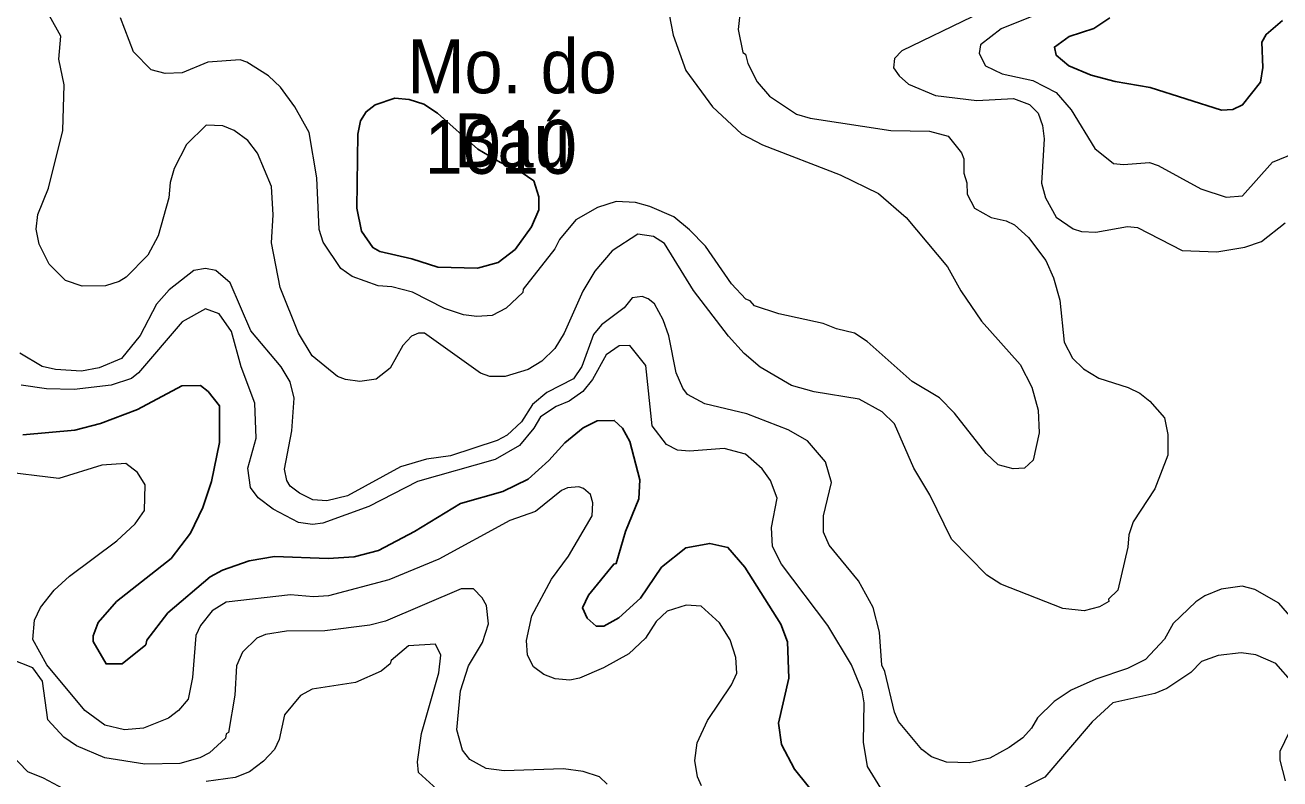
# Model space of a CAD drawing. Extents: x 447.8 to 473.9, y 7733.1 to 7760.8.
# Drawn here: x 457.538 to 459.4, y 7756.505 to 7757.624 of the extents above; entities that cross this region are included whole.
import ezdxf
from ezdxf.enums import TextEntityAlignment as Align

# ---------------------------------------------------------------- set-up
doc = ezdxf.new("R2010")
doc.units = 0
doc.header["$LTSCALE"] = 0.032
doc.layers.add('1', color=7, linetype='Continuous', lineweight=25)
doc.layers.add('2', color=7, linetype='Continuous', lineweight=13)
doc.layers.add('21', color=7, linetype='Continuous')
doc.layers.add('27', color=7, linetype='Continuous')

msp = doc.modelspace()

# ---------------------------------------------------------------- linework, layer by layer
at = {"layer": '1'}
for points in [[(459.4043, 7757.6305), (459.38, 7757.6098), (459.3736, 7757.5982), (459.375, 7757.5608), (459.3716, 7757.5389), (459.3451, 7757.5054), (459.3305, 7757.4984), (459.3139, 7757.4976), (459.208, 7757.5312), (459.1558, 7757.5399), (459.1201, 7757.5495), (459.087, 7757.5633), (459.0683, 7757.5789), (459.0657, 7757.5909), (459.0874, 7757.6065), (459.1242, 7757.6186), (459.148, 7757.6342)], [(457.5343, 7757.0158), (457.6113, 7757.0229), (457.6497, 7757.0324), (457.7043, 7757.0533), (457.7704, 7757.0886), (457.7978, 7757.0892), (457.8094, 7757.08), (457.8264, 7757.059), (457.8264, 7757.0045), (457.8144, 7756.9468), (457.8014, 7756.908), (457.7831, 7756.8699), (457.7544, 7756.8324), (457.6731, 7756.7685), (457.6461, 7756.7375), (457.6389, 7756.7176), (457.6389, 7756.7091), (457.6579, 7756.6759), (457.6818, 7756.6759), (457.7169, 7756.7043), (457.7183, 7756.7111), (457.7497, 7756.7515), (457.8122, 7756.8052), (457.8309, 7756.8152), (457.8701, 7756.829), (457.9079, 7756.8353), (457.9877, 7756.8323), (458.0262, 7756.8349), (458.0621, 7756.8442), (458.1157, 7756.8726), (458.184, 7756.9139), (458.2468, 7756.9317), (458.2846, 7756.9499), (458.315, 7756.9776), (458.3389, 7757.004), (458.3659, 7757.0261), (458.3871, 7757.0365), (458.4123, 7757.0372), (458.4246, 7757.0258), (458.4356, 7757.0061), (458.45, 7756.9488), (458.4485, 7756.921), (458.4287, 7756.8722), (458.4152, 7756.8251), (458.4114, 7756.8238), (458.3738, 7756.7781), (458.3653, 7756.7591), (458.372, 7756.7439), (458.3852, 7756.7321), (458.3968, 7756.732), (458.4191, 7756.7442), (458.4514, 7756.7733), (458.4824, 7756.8196), (458.5183, 7756.8482), (458.5539, 7756.8546), (458.581, 7756.8487), (458.6061, 7756.8196), (458.6597, 7756.735), (458.6695, 7756.7087), (458.6712, 7756.6547), (458.6561, 7756.588), (458.6603, 7756.5563), (458.6799, 7756.5197), (458.7448, 7756.439)]]:
    msp.add_lwpolyline(points, dxfattribs=at)
msp.add_lwpolyline([(458.1497, 7757.4932), (458.1293, 7757.5062), (458.1078, 7757.5131), (458.0866, 7757.5152), (458.0573, 7757.5055), (458.044, 7757.4952), (458.0357, 7757.4814), (458.0317, 7757.4618), (458.0301, 7757.3521), (458.037, 7757.3179), (458.0536, 7757.2935), (458.0643, 7757.2876), (458.1116, 7757.2771), (458.1505, 7757.2647), (458.2092, 7757.2631), (458.24, 7757.2716), (458.265, 7757.2909), (458.2896, 7757.3242), (458.3004, 7757.3496), (458.3004, 7757.3689), (458.2928, 7757.3924), (458.266, 7757.4107), (458.2435, 7757.4196), (458.2098, 7757.4395)], close=True, dxfattribs=at)
at = {"layer": '2'}
for points in [[(459.0644, 7757.2487), (459.0736, 7757.2158), (459.0803, 7757.1531), (459.0924, 7757.1294), (459.1087, 7757.1139), (459.1316, 7757.0998), (459.175, 7757.0861), (459.1923, 7757.0775), (459.2073, 7757.0656), (459.229, 7757.0408), (459.2341, 7757.0163), (459.234, 7756.9856), (459.2147, 7756.9356), (459.1825, 7756.8869), (459.176, 7756.8672), (459.1746, 7756.849), (459.1596, 7756.7856), (459.1461, 7756.772), (459.1463, 7756.7687), (459.1325, 7756.7606), (459.1096, 7756.7545), (459.0779, 7756.7584), (458.9859, 7756.7944), (458.9652, 7756.8077), (458.913, 7756.8608), (458.8809, 7756.9269), (458.8571, 7756.9661), (458.8285, 7757.0323), (458.8101, 7757.0501), (458.7758, 7757.0685), (458.7092, 7757.0796), (458.6752, 7757.0892), (458.6289, 7757.1162), (458.6049, 7757.1366), (458.5819, 7757.1622), (458.5298, 7757.2297), (458.487, 7757.2995), (458.4706, 7757.31), (458.4473, 7757.3134), (458.4089, 7757.2887), (458.3832, 7757.2584), (458.3654, 7757.2288), (458.338, 7757.1667), (458.324, 7757.1438), (458.3047, 7757.1252), (458.2844, 7757.1125), (458.2503, 7757.1024), (458.2276, 7757.1024), (458.2139, 7757.1071), (458.1306, 7757.1664), (458.1214, 7757.1664), (458.111, 7757.1624), (458.0983, 7757.1483), (458.0795, 7757.1149), (458.0589, 7757.0984), (458.0343, 7757.0951), (458.0131, 7757.0977), (458.0012, 7757.1024), (457.9636, 7757.133), (457.9433, 7757.1667), (457.9161, 7757.2344), (457.9034, 7757.3004), (457.9058, 7757.3423), (457.9033, 7757.3841), (457.8827, 7757.4335), (457.8684, 7757.4523), (457.8479, 7757.4674), (457.8314, 7757.4742), (457.8066, 7757.4754), (457.7771, 7757.4464), (457.7589, 7757.4111), (457.7528, 7757.3899), (457.7511, 7757.3672), (457.7351, 7757.311), (457.72, 7757.2821), (457.6875, 7757.2497), (457.6775, 7757.2431), (457.6568, 7757.237), (457.6221, 7757.2363), (457.5976, 7757.2448), (457.5732, 7757.2688), (457.5585, 7757.2986), (457.5539, 7757.3207), (457.5563, 7757.3425), (457.5724, 7757.3815), (457.5938, 7757.4675), (457.5955, 7757.5348), (457.5876, 7757.5733), (457.5907, 7757.607), (457.5572, 7757.6678)], [(458.4878, 7757.6705), (458.4998, 7757.6086), (458.5183, 7757.5565), (458.5579, 7757.5026), (458.601, 7757.4623), (458.6324, 7757.446), (458.7476, 7757.4016), (458.8043, 7757.374), (458.8455, 7757.3384), (458.9069, 7757.2651), (458.9267, 7757.2295), (458.9572, 7757.1843), (459.0149, 7757.1202), (459.0319, 7757.0865), (459.0416, 7757.0526), (459.0432, 7757.0189), (459.0342, 7756.9783), (459.0214, 7756.9662), (459.0044, 7756.9653), (458.9822, 7756.9711), (458.9641, 7756.9883), (458.9171, 7757.0481), (458.8952, 7757.0708), (458.8546, 7757.0948), (458.7878, 7757.1542), (458.7691, 7757.1667), (458.7421, 7757.1728), (458.7223, 7757.1809), (458.6565, 7757.1954), (458.6203, 7757.2073), (458.6142, 7757.2145), (458.6075, 7757.2169), (458.5864, 7757.2397), (458.5475, 7757.2957), (458.5241, 7757.3201), (458.5007, 7757.3391), (458.465, 7757.3544), (458.4436, 7757.3604), (458.4149, 7757.362), (458.3872, 7757.3531), (458.3552, 7757.3345), (458.3311, 7757.3057), (458.3242, 7757.2916), (458.2768, 7757.232), (458.2765, 7757.2269), (458.2518, 7757.2038), (458.2309, 7757.1926), (458.2084, 7757.1913), (458.1884, 7757.1938), (458.1601, 7757.2032), (458.1129, 7757.2272), (458.082, 7757.2352), (458.0618, 7757.237), (458.023, 7757.2509), (458.0063, 7757.2624), (457.9801, 7757.3018), (457.974, 7757.3203), (457.9708, 7757.397), (457.9595, 7757.4643), (457.9382, 7757.5025), (457.9167, 7757.5314), (457.8988, 7757.5486), (457.8668, 7757.5687), (457.8569, 7757.572), (457.8088, 7757.5688), (457.771, 7757.553), (457.7457, 7757.5516), (457.7246, 7757.5574), (457.6983, 7757.5838), (457.679, 7757.6342)], [(458.5998, 7757.6485), (458.596, 7757.617), (458.6031, 7757.583), (458.6071, 7757.5804), (458.6104, 7757.5666), (458.6242, 7757.5397), (458.6427, 7757.5181), (458.6828, 7757.4917), (458.703, 7757.4855), (458.8229, 7757.4671), (458.8801, 7757.4662), (458.9077, 7757.4589), (458.9278, 7757.4339), (458.931, 7757.425), (458.9311, 7757.4041), (458.9358, 7757.3895), (458.9359, 7757.3728), (458.9471, 7757.3518), (458.9716, 7757.3384)], [(458.9436, 7757.636), (458.839, 7757.5854), (458.8284, 7757.5741), (458.827, 7757.5602), (458.8351, 7757.5485), (458.8492, 7757.536), (458.889, 7757.5193), (458.9507, 7757.512), (459.0047, 7757.5145), (459.0285, 7757.5056), (459.0414, 7757.4928), (459.048, 7757.4745), (459.0503, 7757.4549), (459.0465, 7757.3893), (459.0526, 7757.3675), (459.0682, 7757.3386), (459.0933, 7757.3213), (459.1059, 7757.3176), (459.1273, 7757.3164), (459.174, 7757.325), (459.1888, 7757.3235), (459.2554, 7757.2894), (459.3068, 7757.2875), (459.3484, 7757.2941), (459.3731, 7757.3026), (459.4083, 7757.3301)], [(459.0347, 7757.6375), (458.9868, 7757.6182)], [(458.9868, 7757.6182), (458.9561, 7757.5943), (458.954, 7757.5813), (458.9632, 7757.5634), (458.988, 7757.5515), (459.0338, 7757.5413)], [(459.0338, 7757.5413), (459.0684, 7757.5236), (459.0903, 7757.4979), (459.1257, 7757.4406), (459.1536, 7757.4182), (459.1683, 7757.4166), (459.2069, 7757.4199), (459.2198, 7757.4155), (459.2831, 7757.3807), (459.3205, 7757.3685), (459.3447, 7757.3704), (459.3896, 7757.4203), (459.4416, 7757.4416)], [(458.9716, 7757.3384), (458.994, 7757.3335), (459.0066, 7757.3273), (459.027, 7757.3086), (459.053, 7757.2743), (459.0644, 7757.2487)], [(458.3121, 7757.0787), (458.291, 7757.061), (458.2747, 7757.0349), (458.2534, 7757.0152), (458.2386, 7757.0075), (458.1691, 7756.9844), (458.1336, 7756.9795), (458.0951, 7756.9682), (458.0162, 7756.9254), (457.9854, 7756.918), (457.9648, 7756.9194), (457.9448, 7756.9293), (457.9313, 7756.9398), (457.926, 7756.9481), (457.9227, 7756.965), (457.9338, 7757.0218), (457.937, 7757.0702), (457.9313, 7757.0946), (457.9177, 7757.1167), (457.8728, 7757.1699), (457.842, 7757.2413), (457.8206, 7757.2598), (457.8054, 7757.2625), (457.7883, 7757.2594), (457.7516, 7757.2311), (457.7327, 7757.2097), (457.7086, 7757.1633), (457.6807, 7757.1289), (457.6476, 7757.1151), (457.6215, 7757.1104), (457.5828, 7757.1127), (457.5629, 7757.117), (457.53, 7757.1369)], [(459.4215, 7756.74), (459.3988, 7756.766), (459.363, 7756.7864), (459.3442, 7756.7913), (459.3131, 7756.7866), (459.2891, 7756.7771), (459.2756, 7756.7679), (459.2419, 7756.7359), (459.229, 7756.7125), (459.2008, 7756.6825), (459.1741, 7756.6692), (459.1269, 7756.6535), (459.0906, 7756.6372), (459.0654, 7756.6203), (459.0405, 7756.5962), (459.0316, 7756.5808), (459.0188, 7756.5665), (458.9986, 7756.5518), (458.97, 7756.5362), (458.939, 7756.5292), (458.9054, 7756.53), (458.8832, 7756.5379), (458.8689, 7756.5488), (458.8344, 7756.5907), (458.8282, 7756.6043), (458.8139, 7756.6646), (458.8093, 7756.674), (458.8058, 7756.723), (458.7967, 7756.7598), (458.7746, 7756.7991), (458.7312, 7756.8521), (458.7227, 7756.8715), (458.7227, 7756.8955), (458.7347, 7756.9452), (458.7258, 7756.9756), (458.6993, 7757.0069), (458.6705, 7757.023), (458.6088, 7757.0467), (458.5468, 7757.062), (458.5209, 7757.0755), (458.514, 7757.0849), (458.5043, 7757.1077), (458.4934, 7757.1629), (458.4848, 7757.1866), (458.4719, 7757.21), (458.4628, 7757.2177), (458.4535, 7757.2208), (458.4389, 7757.2192), (458.4267, 7757.204)], [(457.8054, 7757.2029), (457.771, 7757.1836), (457.7061, 7757.1079), (457.6955, 7757.0996), (457.6653, 7757.0893), (457.6107, 7757.0831), (457.5693, 7757.0839), (457.5316, 7757.0897)], [(457.8808, 7757.011), (457.8785, 7757.063), (457.8584, 7757.1167), (457.844, 7757.1691), (457.8258, 7757.1954), (457.8054, 7757.2029)], [(458.4267, 7757.204), (458.3931, 7757.1791), (458.3812, 7757.1648), (458.3643, 7757.117), (458.3519, 7757.0991), (458.3121, 7757.0787)], [(458.8081, 7756.4918), (458.7884, 7756.5236), (458.782, 7756.5597), (458.7832, 7756.6183), (458.7802, 7756.6358), (458.7646, 7756.6748), (458.7291, 7756.7329), (458.6605, 7756.8241), (458.647, 7756.8499), (458.6457, 7756.8781), (458.6542, 7756.9218), (458.6441, 7756.948), (458.6318, 7756.9652), (458.6069, 7756.987), (458.5754, 7756.9955), (458.5237, 7756.9918), (458.5063, 7756.9931), (458.49, 7757.0015), (458.4684, 7757.0293), (458.4592, 7757.1185), (458.4353, 7757.1484), (458.4197, 7757.1477), (458.4002, 7757.1345), (458.3798, 7757.0981), (458.3658, 7757.0799), (458.3453, 7757.0656), (458.3262, 7757.0579), (458.3026, 7757.0427), (458.2929, 7757.0258), (458.2718, 7756.9998), (458.2356, 7756.9793), (458.1199, 7756.9467), (458.0478, 7756.9093), (457.9798, 7756.8846), (457.9642, 7756.8828), (457.9433, 7756.8858), (457.906, 7756.9053), (457.8835, 7756.9225), (457.8721, 7756.9375), (457.8682, 7756.9664), (457.8808, 7757.011)], [(457.7043, 7756.9599), (457.687, 7756.9733), (457.6516, 7756.9708), (457.5875, 7756.9509), (457.4974, 7756.9621)], [(457.6033, 7756.8062), (457.6739, 7756.8584), (457.7009, 7756.8837), (457.715, 7756.9035), (457.7157, 7756.9417), (457.7043, 7756.9599)], [(458.5418, 7756.4953), (458.5357, 7756.5083), (458.5319, 7756.5325), (458.5351, 7756.559), (458.5505, 7756.5921), (458.5865, 7756.6449), (458.5942, 7756.6621), (458.5927, 7756.6855), (458.5844, 7756.7118), (458.5684, 7756.7371), (458.5412, 7756.7615), (458.5189, 7756.7631), (458.4909, 7756.7544), (458.4745, 7756.7389), (458.4588, 7756.7143), (458.4338, 7756.6908), (458.3965, 7756.6699), (458.3605, 7756.6549), (458.3462, 7756.6519), (458.3245, 7756.654), (458.3077, 7756.6604), (458.2924, 7756.6718), (458.2834, 7756.6887), (458.2818, 7756.7108), (458.29, 7756.7471), (458.3191, 7756.8019), (458.3442, 7756.8357), (458.3795, 7756.8956), (458.3803, 7756.9147), (458.3771, 7756.9272), (458.3666, 7756.9363), (458.3597, 7756.9386), (458.343, 7756.9371), (458.3341, 7756.9333), (458.2953, 7756.902), (458.2573, 7756.8889), (458.1517, 7756.8312), (458.0775, 7756.8007), (457.988, 7756.7768), (457.9656, 7756.7753), (457.9315, 7756.7784), (457.836, 7756.7678), (457.8154, 7756.7546), (457.798, 7756.7329), (457.7912, 7756.7182), (457.7863, 7756.6559), (457.7799, 7756.6238), (457.7653, 7756.6067), (457.7503, 7756.5954), (457.7133, 7756.5806), (457.685, 7756.5782), (457.6562, 7756.5852), (457.6261, 7756.6069), (457.5697, 7756.6745), (457.5491, 7756.7122), (457.5516, 7756.7407), (457.5607, 7756.7595), (457.581, 7756.7854), (457.6033, 7756.8062)], [(458.4018, 7756.4978), (458.3901, 7756.5086), (458.3659, 7756.5162), (458.337, 7756.5203), (458.2489, 7756.5172), (458.2221, 7756.5209), (458.1976, 7756.5341), (458.1869, 7756.5482), (458.1784, 7756.578), (458.184, 7756.6359), (458.1958, 7756.6731), (458.2167, 7756.7077), (458.2256, 7756.7354), (458.2226, 7756.7625), (458.2161, 7756.7738), (458.2031, 7756.7871), (458.1852, 7756.7871), (458.0724, 7756.7395), (458.0492, 7756.7335), (457.9826, 7756.7248), (457.9255, 7756.7247), (457.8946, 7756.7198), (457.8818, 7756.7143), (457.8605, 7756.6932), (457.8513, 7756.6733), (457.8489, 7756.6297)], [(458.1597, 7756.4802), (458.1216, 7756.515), (458.12, 7756.5306), (458.1261, 7756.5725), (458.1518, 7756.6627), (458.1549, 7756.6888), (458.1471, 7756.7051), (458.107, 7756.703), (458.0809, 7756.681), (458.0797, 7756.6762), (458.0663, 7756.6654), (458.0281, 7756.6486), (457.9637, 7756.6387), (457.9465, 7756.629), (457.9225, 7756.6002), (457.9146, 7756.5637), (457.9079, 7756.549), (457.8916, 7756.5317), (457.8707, 7756.516), (457.8493, 7756.5073), (457.8063, 7756.5013)], [(457.797, 7756.5366), (457.7675, 7756.5284), (457.7153, 7756.5274), (457.6562, 7756.5365), (457.6141, 7756.5546), (457.595, 7756.5674), (457.5715, 7756.5928), (457.5635, 7756.6502), (457.5492, 7756.6699), (457.5164, 7756.6831)], [(459.4086, 7756.5027), (459.4008, 7756.5331), (459.4008, 7756.5463), (459.4221, 7756.5905), (459.4278, 7756.6102), (459.4267, 7756.6342), (459.4194, 7756.648), (459.3941, 7756.6764), (459.3649, 7756.6893), (459.3431, 7756.6926), (459.3085, 7756.6884), (459.2838, 7756.6793), (459.2683, 7756.6631), (459.2327, 7756.6393), (459.2147, 7756.6321), (459.1523, 7756.618), (459.1217, 7756.5901), (459.0513, 7756.5078), (458.9975, 7756.4807)], [(457.8489, 7756.6297), (457.8394, 7756.574), (457.8362, 7756.5723), (457.8352, 7756.566), (457.8114, 7756.5441), (457.797, 7756.5366)], [(457.6315, 7756.4708), (457.5651, 7756.5067), (457.5416, 7756.5159), (457.4737, 7756.5856)]]:
    msp.add_lwpolyline(points, dxfattribs=at)

# ---------------------------------------------------------------- texts
at = {"layer": '21', "width": 0.95}
msp.add_text('1010', height=0.08, dxfattribs=at).set_placement((458.1308, 7757.403))
at = {"layer": '27'}
for s, width, p in [('Mo. do', 0.95, (458.2606, 7757.5225)), ('Baú', 0.9, (458.2606, 7757.4125))]:
    msp.add_text(s, height=0.08, dxfattribs=dict(at, width=width)).set_placement(p, align=Align.CENTER)

doc.saveas('drawing.dxf')
